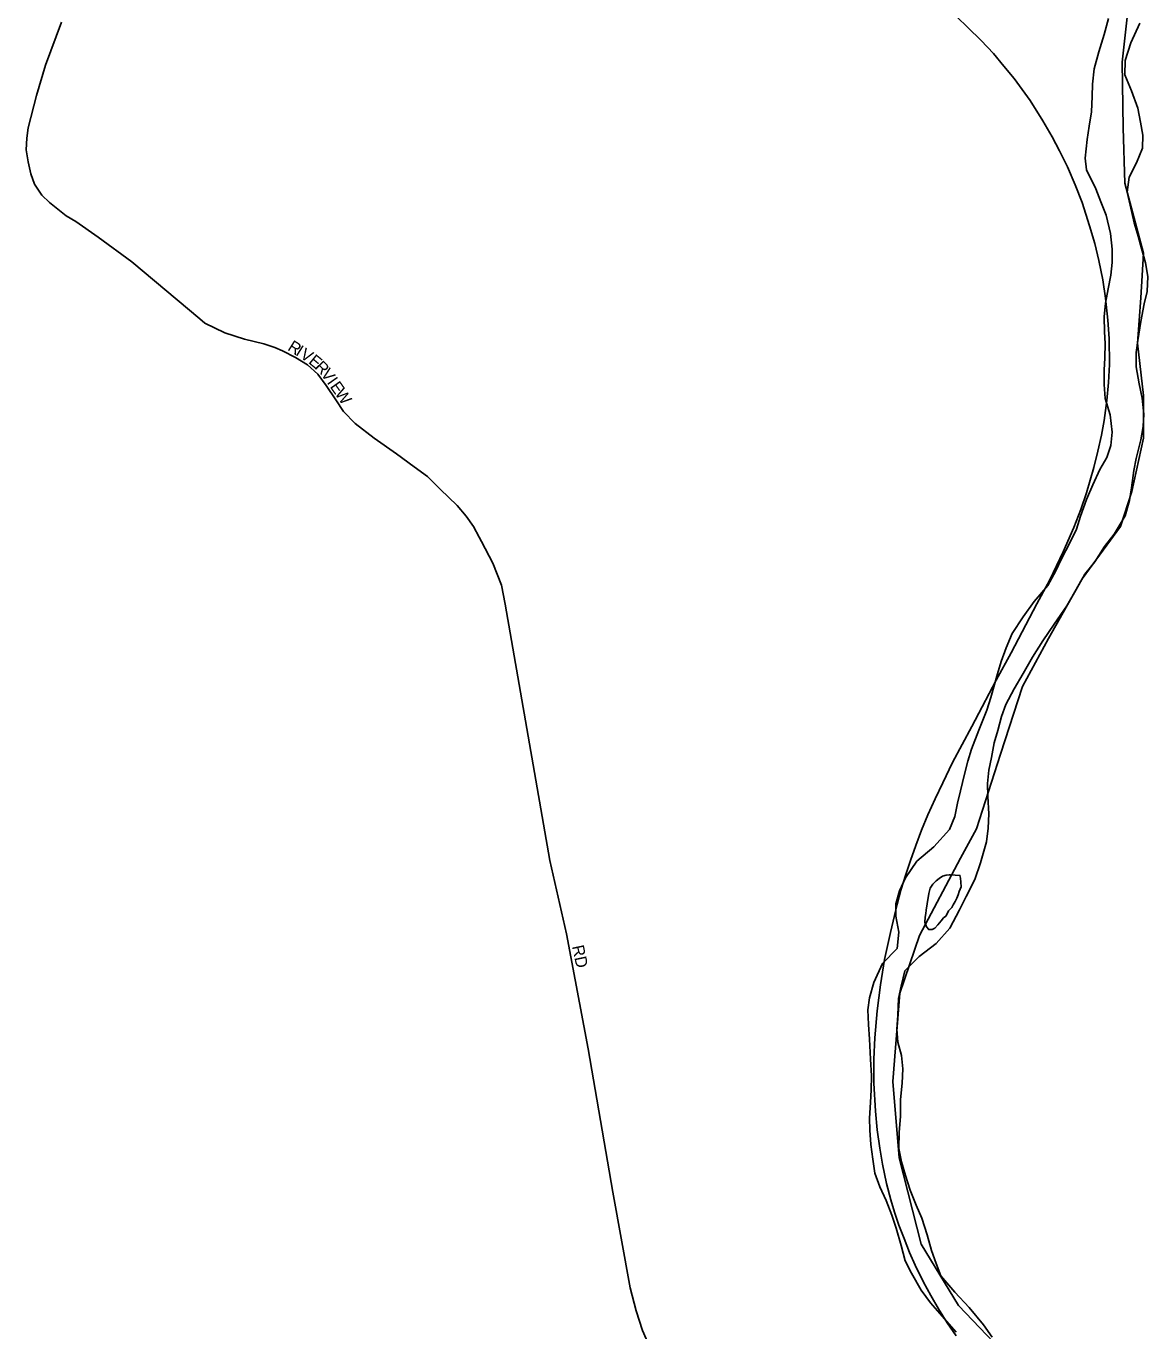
# Model space of a CAD drawing. Extents: x -561 to 1170, y 0 to 846.
# Drawn here: x 309.36 to 322.12, y 119.17 to 134.01 of the extents above; entities that cross this region are included whole.
import ezdxf

# ---------------------------------------------------------------- set-up
doc = ezdxf.new("R2010")
doc.units = 0
for name, color, linetype in [('GM_X_City_Street', 7, 'Continuous'), ('GM_X_City_Street_Text', 7, 'Continuous'), ('GM_X_County', 7, 'Continuous'), ('GM_X_Major_River', 7, 'Continuous'), ('GM_X_Rail_Line', 7, 'Continuous')]:
    doc.layers.add(name, color=color, linetype=linetype)

msp = doc.modelspace()

# ---------------------------------------------------------------- linework, layer by layer
at = {"layer": 'GM_X_City_Street'}
for points in [[(311.335, 130.677), (310.562, 131.326), (310.179, 131.609), (309.923, 131.786), (309.812, 131.85), (309.624, 132.003), (309.535, 132.087), (309.455, 132.209), (309.413, 132.328), (309.381, 132.463), (309.358, 132.6), (309.365, 132.735), (309.381, 132.851), (309.474, 133.218), (309.579, 133.562), (309.762, 134.051)], [(314.51, 128.195), (314.446, 128.317), (314.364, 128.436), (314.261, 128.555), (314.069, 128.74), (313.923, 128.885), (313.773, 128.996), (313.569, 129.144), (313.315, 129.321), (313.099, 129.487), (312.969, 129.625), (312.882, 129.757), (312.771, 129.921), (312.676, 130.05), (312.56, 130.156), (312.422, 130.238), (312.272, 130.314), (312.187, 130.352), (312.063, 130.394), (311.841, 130.447), (311.619, 130.518), (311.392, 130.629), (311.335, 130.677)], [(318.543, 115.119), (317.76, 116.483), (317.065, 117.725), (316.896, 118.065), (316.621, 118.591), (316.367, 119.172), (316.296, 119.394), (316.227, 119.656), (316.032, 120.744), (315.752, 122.377), (315.503, 123.683), (315.316, 124.518), (314.806, 127.435), (314.763, 127.651), (314.668, 127.9), (314.536, 128.145), (314.51, 128.195)]]:
    msp.add_lwpolyline(points, dxfattribs=at)
at = {"layer": 'GM_X_County'}
msp.add_lwpolyline([(321.88, 134.109), (321.825, 133.599), (321.835, 132.85), (321.856, 132.223), (322.068, 131.424), (322.038, 130.918), (321.997, 130.402), (322.068, 129.805), (322.068, 129.32), (321.936, 128.713), (321.805, 128.318), (321.37, 127.722), (320.986, 127.044), (320.692, 126.498), (320.439, 125.729), (320.166, 124.879), (319.984, 124.545), (319.519, 123.665), (319.296, 123.008), (319.215, 122.006), (319.286, 121.136), (319.539, 120.155), (319.964, 119.457), (320.763, 118.617)], dxfattribs=at)
at = {"layer": 'GM_X_Major_River'}
for points in [[(321.67, 134.096), (321.618, 133.912), (321.56, 133.716), (321.507, 133.521), (321.487, 133.347), (321.483, 133.206), (321.474, 133.033), (321.448, 132.87), (321.428, 132.718), (321.403, 132.507), (321.42, 132.372), (321.525, 132.156), (321.58, 132.01), (321.641, 131.859), (321.691, 131.648), (321.709, 131.47), (321.71, 131.318), (321.695, 131.177), (321.664, 131.02), (321.633, 130.857), (321.618, 130.7), (321.625, 130.532), (321.632, 130.397), (321.628, 130.234), (321.618, 130.093), (321.62, 129.931), (321.632, 129.774), (321.688, 129.585), (321.711, 129.39), (321.696, 129.238), (321.648, 129.102), (321.569, 128.966), (321.489, 128.792), (321.42, 128.623), (321.352, 128.433), (321.304, 128.286), (321.23, 128.129), (321.134, 127.949), (321.071, 127.813), (320.98, 127.644), (320.825, 127.464), (320.697, 127.289), (320.574, 127.099), (320.505, 126.935), (320.447, 126.783), (320.405, 126.642), (320.332, 126.37), (320.285, 126.229), (320.195, 126.001), (320.11, 125.783), (320.068, 125.648), (320.031, 125.501), (319.984, 125.311), (319.953, 125.17), (319.922, 125.018), (319.859, 124.871), (319.682, 124.674), (319.489, 124.51), (319.361, 124.319), (319.292, 124.172), (319.25, 124.026), (319.251, 123.885), (319.285, 123.701), (319.265, 123.517), (319.099, 123.347), (318.998, 123.13), (318.951, 122.956), (318.931, 122.82), (318.938, 122.652), (318.95, 122.485), (318.963, 122.257), (318.975, 122.068), (318.971, 121.911), (318.961, 121.764), (318.952, 121.586), (318.953, 121.45), (318.966, 121.288), (318.989, 121.12), (319.012, 120.963), (319.067, 120.807), (319.139, 120.65), (319.205, 120.483), (319.255, 120.337), (319.311, 120.137), (319.355, 119.965), (319.427, 119.824), (319.537, 119.63)], [(322.027, 134.04), (321.921, 133.817), (321.858, 133.616), (321.854, 133.454), (321.931, 133.27), (322.003, 133.076), (322.032, 132.914), (322.06, 132.768), (322.056, 132.621), (321.987, 132.453), (321.902, 132.29), (321.882, 132.121), (321.915, 131.97), (321.96, 131.77), (322.005, 131.619), (322.044, 131.478), (322.089, 131.316), (322.117, 131.159), (322.108, 130.991), (322.076, 130.85), (322.035, 130.65), (322.004, 130.433), (321.984, 130.297), (321.985, 130.134), (322.019, 129.94), (322.053, 129.778), (322.071, 129.594), (322.062, 129.453), (322.036, 129.301), (321.984, 129.089), (321.958, 128.953), (321.932, 128.758), (321.907, 128.612), (321.86, 128.438), (321.732, 128.231), (321.625, 128.089), (321.513, 127.915), (321.401, 127.773), (321.299, 127.593), (321.193, 127.413), (321.049, 127.206), (320.921, 127.015), (320.803, 126.83), (320.697, 126.645), (320.596, 126.471), (320.5, 126.291), (320.453, 126.155), (320.411, 125.998), (320.369, 125.856), (320.338, 125.688), (320.307, 125.547), (320.292, 125.395), (320.298, 125.244), (320.306, 125.049), (320.302, 124.886), (320.281, 124.729), (320.213, 124.49), (320.15, 124.3), (320.049, 124.109), (319.975, 123.957), (319.863, 123.75), (319.708, 123.575), (319.514, 123.427), (319.354, 123.263), (319.312, 123.089), (319.281, 122.948), (319.272, 122.759), (319.262, 122.601), (319.274, 122.45), (319.313, 122.299), (319.331, 122.147), (319.322, 121.984), (319.302, 121.8), (319.303, 121.605), (319.289, 121.426), (319.285, 121.242), (319.313, 121.091), (319.358, 120.934), (319.413, 120.767), (319.48, 120.599), (319.546, 120.448), (319.607, 120.259), (319.657, 120.081), (319.707, 119.935), (319.762, 119.795), (319.921, 119.607), (320.084, 119.435), (320.248, 119.236), (320.347, 119.097)], [(319.871, 124.353), (319.979, 124.349), (319.985, 124.316), (319.991, 124.273), (319.992, 124.219), (319.981, 124.192), (319.971, 124.164), (319.96, 124.126), (319.945, 124.088), (319.923, 124.05), (319.902, 124.012), (319.886, 123.984), (319.849, 123.946), (319.839, 123.919), (319.817, 123.886), (319.791, 123.864), (319.764, 123.831), (319.727, 123.787), (319.695, 123.749), (319.662, 123.732), (319.625, 123.732), (319.597, 123.764), (319.58, 123.818), (319.585, 123.872), (319.59, 123.916), (319.595, 123.954), (319.617, 124.098)], [(319.871, 124.353), (319.979, 124.349), (319.985, 124.316), (319.991, 124.273), (319.992, 124.219), (319.981, 124.192), (319.971, 124.164), (319.96, 124.126), (319.945, 124.088), (319.923, 124.05), (319.902, 124.012), (319.886, 123.984), (319.849, 123.946), (319.839, 123.919), (319.817, 123.886), (319.791, 123.864), (319.764, 123.831), (319.727, 123.787), (319.695, 123.749), (319.662, 123.732), (319.625, 123.732), (319.597, 123.764), (319.58, 123.818), (319.585, 123.872), (319.59, 123.916), (319.595, 123.954), (319.617, 124.098)], [(319.617, 124.098), (319.62, 124.117), (319.625, 124.144), (319.64, 124.204), (319.672, 124.247), (319.709, 124.286), (319.741, 124.313), (319.779, 124.341), (319.822, 124.352), (319.855, 124.353), (319.871, 124.353)], [(319.617, 124.098), (319.62, 124.117), (319.625, 124.144), (319.64, 124.204), (319.672, 124.247), (319.709, 124.286), (319.741, 124.313), (319.779, 124.341), (319.822, 124.352), (319.855, 124.353), (319.871, 124.353)], [(319.537, 119.63), (319.646, 119.485), (319.804, 119.303), (319.935, 119.152)]]:
    msp.add_lwpolyline(points, dxfattribs=at)
at = {"layer": 'GM_X_Rail_Line'}
msp.add_lwpolyline([(319.938, 119.111), (319.833, 119.26), (319.736, 119.419), (319.648, 119.57), (319.564, 119.723), (319.471, 119.916), (319.407, 120.059), (319.344, 120.217), (319.284, 120.37), (319.235, 120.518), (319.194, 120.657), (319.143, 120.844), (319.097, 121.064), (319.068, 121.244), (319.036, 121.453), (319.018, 121.666), (319, 121.987), (319, 122.259), (319.012, 122.499), (319.037, 122.809), (319.076, 123.102), (319.121, 123.391), (319.188, 123.7), (319.266, 124.022), (319.306, 124.18), (319.362, 124.358), (319.415, 124.517), (319.476, 124.69), (319.542, 124.863), (319.614, 125.038), (319.697, 125.218), (319.783, 125.402), (319.896, 125.632), (320.003, 125.837), (320.114, 126.043), (320.233, 126.265), (320.392, 126.569), (320.561, 126.878), (320.855, 127.436), (321, 127.711), (321.152, 128.028), (321.273, 128.304), (321.354, 128.511), (321.417, 128.699), (321.503, 128.986), (321.549, 129.173), (321.59, 129.357), (321.618, 129.523), (321.648, 129.75), (321.668, 129.956), (321.679, 130.16), (321.676, 130.455), (321.662, 130.664), (321.636, 130.914), (321.604, 131.122), (321.558, 131.343), (321.512, 131.536), (321.454, 131.735), (321.369, 132.001), (321.29, 132.203), (321.201, 132.408), (321.112, 132.591), (321.028, 132.75), (320.923, 132.929), (320.776, 133.161), (320.597, 133.412), (320.48, 133.553), (320.359, 133.696), (320.222, 133.844), (320.07, 133.994), (319.943, 134.113)], dxfattribs=at)

# ---------------------------------------------------------------- texts
at = {"layer": 'GM_X_City_Street_Text'}
for s, rotation, p in [('R', 327.7449, (312.323, 130.329)), ('I', 327.7469, (312.414, 130.272)), ('V', 327.7467, (312.464, 130.241)), ('E', 320.8452, (312.561, 130.18)), ('R', 314.4848, (312.632, 130.122)), ('V', 306.6863, (312.703, 130.05)), ('I', 305.1819, (312.774, 129.955)), ('E', 305.1817, (312.808, 129.907)), ('W', 304.5761, (312.863, 129.829)), ('RD', 281.895, (315.566, 123.541))]:
    msp.add_text(s, height=0.135, rotation=rotation, dxfattribs=at).set_placement(p)

doc.saveas('drawing.dxf')
